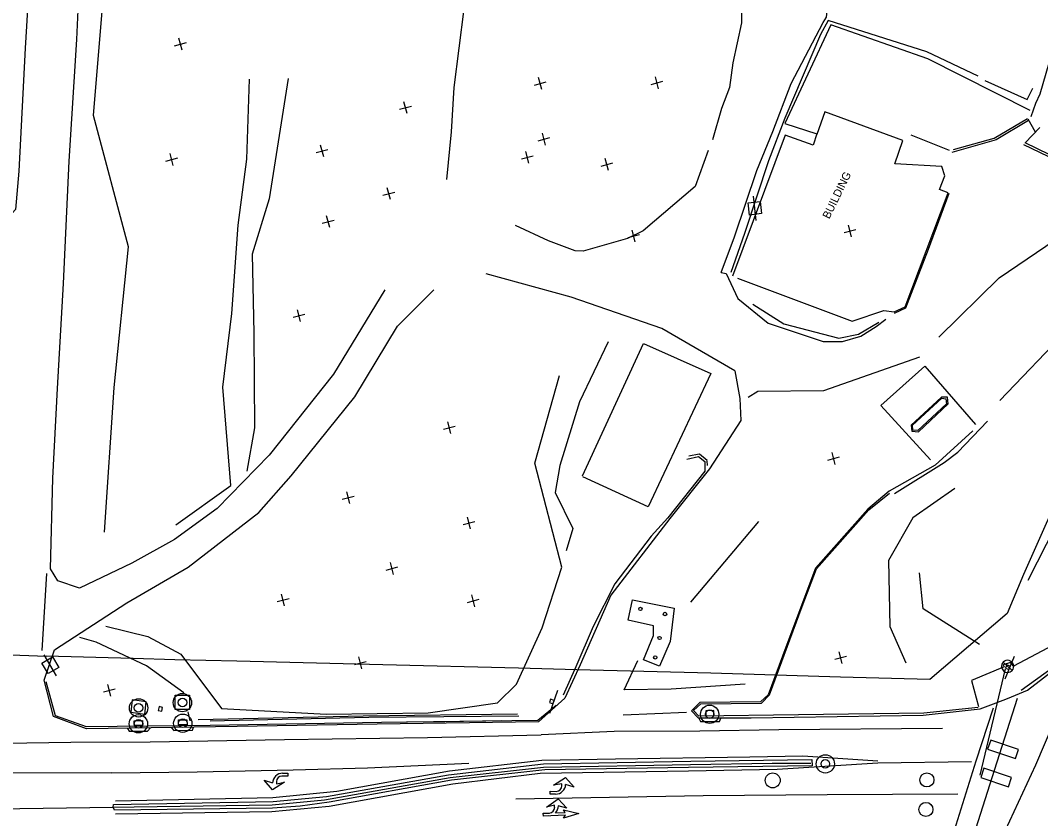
# Model space of a CAD drawing. Extents: x 4711259 to 4716401, y 890074 to 892728.
# Drawn here: x 4712586.5 to 4713004.8, y 891346.1 to 891673.4 of the extents above; entities that cross this region are included whole.
import ezdxf

# ---------------------------------------------------------------- set-up
doc = ezdxf.new("R2010")
doc.units = 0
for name, color, linetype in [('E_GT_WALL_Retaining', 7, 'Continuous'), ('E_HY_STORM_MH', 7, 'Continuous'), ('E_RDWY_PHOTOG_Fence', 7, 'Continuous'), ('E_RDWY_ROAD_Curb', 7, 'Continuous'), ('E_RDWY_ROAD_EdgeAsph', 7, 'Continuous'), ('E_RDWY_ROAD_EdgeConc', 7, 'Continuous'), ('E_RDWY_ROAD_Sidewalk', 7, 'Continuous'), ('E_RDWY_ROAD_Striping', 7, 'Continuous'), ('E_RDWY_ROAD_TBofCurb', 7, 'Continuous'), ('E_TERR_DTM_BrkLines', 7, 'Continuous'), ('E_TERR_DTM_RandomPt', 7, 'Continuous'), ('E_TRAF_PHOTOG_SignalEquipment', 7, 'Continuous'), ('E_TRAF_SIGN_PublicSign', 7, 'Continuous'), ('E_TRAF_SIGNAL_Detector', 7, 'Continuous'), ('E_TRAF_SIGNAL_Equipment', 7, 'Continuous'), ('E_TRAF_SIGNAL_Poles', 7, 'Continuous'), ('E_UTIL_ELEC_POLE', 7, 'Continuous'), ('E_UTIL_MISC_General', 7, 'Continuous')]:
    doc.layers.add(name, color=color, linetype=linetype)

msp = doc.modelspace()

# ---------------------------------------------------------------- linework, layer by layer
at = {"layer": 'E_GT_WALL_Retaining'}
for points in [[(4713000.6, 891636.44), (4712958.58, 891657.64), (4712918.87, 891671.59), (4712899.88, 891631.11), (4712913.06, 891626.79), (4712911.51, 891622.16), (4712900.07, 891626.31), (4712878.42, 891568.51)], [(4712886.81, 891556.96), (4712899.57, 891548.97), (4712922.14, 891543.04), (4712930.16, 891544.73), (4712938.48, 891549.58)], [(4712944.94, 891479.32), (4712965.31, 891492.06), (4712970.91, 891496.37), (4712983.11, 891508.97)], [(4712790.29, 891388.82), (4712726.99, 891388.01), (4712659.31, 891386.58)]]:
    msp.add_lwpolyline(points, dxfattribs=at)
at = {"layer": 'E_HY_STORM_MH'}
for centre, radius in [((4712652.9, 891393.63), 3.75), ((4712634.93, 891391.46), 3.75), ((4712634.93, 891391.46), 1.76), ((4712652.9, 891393.63), 1.76), ((4712869.13, 891388.84), 3.75), ((4712634.85, 891384.94), 3.75), ((4712653.06, 891385.17), 3.75), ((4712869.13, 891388.84), 1.76), ((4712634.85, 891384.94), 1.76), ((4712653.06, 891385.17), 1.76), ((4712916.54, 891368.51), 3.75), ((4712916.54, 891368.51), 1.76)]:
    msp.add_circle(centre, radius, dxfattribs=at)
at = {"layer": 'E_RDWY_PHOTOG_Fence'}
for points in [[(4713045.7, 891553.22), (4713017.05, 891489.52), (4712997.81, 891446.2), (4712991.1, 891430.18)], [(4712991.1, 891430.18), (4712959.4, 891403.14), (4712922.81, 891404.01), (4712869.56, 891405.64), (4712814.66, 891407.03), (4712790.78, 891407.74), (4712735.13, 891409.08), (4712675.26, 891410.61), (4712649.85, 891411.15), (4712632.67, 891411.67), (4712597.09, 891412.69)], [(4712597.22, 891412.51), (4712575.15, 891413.33)]]:
    msp.add_lwpolyline(points, dxfattribs=at)
at = {"layer": 'E_RDWY_ROAD_Curb'}
for p, q in [((4712864.87, 891495.53), (4712860.62, 891494.71)), ((4712868.05, 891492.84), (4712864.95, 891495.54)), ((4712868.16, 891490.86), (4712868.09, 891492.8))]:
    msp.add_line(p, q, dxfattribs=at)
for points in [[(4712999.8, 891632.38), (4712986.67, 891624.45), (4712968.37, 891619.16)], [(4712997.75, 891622.46), (4713007.83, 891617.64), (4713018.22, 891604.67), (4713051.59, 891591.3), (4713075.27, 891585.61), (4713090.25, 891583.37)], [(4712944.91, 891553.35), (4712949.62, 891555.57), (4712958.85, 891579.56), (4712967.29, 891602.46)], [(4712977.01, 891505.08), (4712961.64, 891491.03), (4712942.78, 891480.29), (4712933.91, 891472.94), (4712912.52, 891448.76), (4712900.38, 891416.37), (4712893.05, 891396.84), (4712889.9, 891393.91), (4712865.15, 891393.67), (4712861.69, 891390.31), (4712864.41, 891387.4), (4712886.12, 891387.44), (4712956.66, 891388.43), (4712980.08, 891391.03), (4712986.65, 891393.54), (4712991.2, 891395.3), (4712999.39, 891398.78), (4713017.42, 891412.56), (4713027.96, 891425.91), (4713046.57, 891464.61), (4713070.7, 891516.01), (4713080.81, 891539.89)], [(4712798.86, 891385.79), (4712732.79, 891384.81), (4712675.36, 891383.82), (4712613.58, 891382.94), (4712600.05, 891387.87), (4712596.16, 891402.85)], [(4712624.67, 891351.82), (4712690.06, 891353.11), (4712711.98, 891355.18), (4712762, 891364.01), (4712800.91, 891368.54), (4712861.39, 891369.55), (4712911, 891370.33), (4712911.16, 891367.74), (4712860.5, 891367.03), (4712801.52, 891366.02), (4712763.21, 891361.88), (4712713.08, 891352.78), (4712701.15, 891351.21), (4712689.82, 891350.35), (4712625.05, 891349.47)], [(4712625.05, 891349.47), (4712624.53, 891350.79), (4712624.67, 891351.82)]]:
    msp.add_lwpolyline(points, dxfattribs=at)
at = {"layer": 'E_RDWY_ROAD_EdgeAsph'}
for points in [[(4712735.9, 891562.86), (4712714.82, 891528.34), (4712688.44, 891495.14), (4712667.15, 891473.19), (4712649.72, 891460.53), (4712632.13, 891450.87), (4712610.67, 891440.52), (4712601.83, 891443.5), (4712598.88, 891448.47), (4712599.81, 891485.64), (4712601.62, 891522.38), (4712604.11, 891565.54), (4712606.51, 891615.64), (4712609.62, 891665.6), (4712611.64, 891710.78), (4712614.55, 891772.4), (4712618.2, 891830.11), (4712619.55, 891857.41), (4712617.18, 891894.05), (4712611.49, 891911.96), (4712575.66, 891948.29)], [(4712304.96, 891896.85), (4712384.63, 891896.03), (4712434.12, 891895.34), (4712491.07, 891894.75), (4712543.41, 891894.49), (4712582.4, 891892.24), (4712597.63, 891878.83), (4712597.65, 891831.39), (4712594.45, 891776.63), (4712591.79, 891718.65), (4712588.49, 891662.05), (4712585.87, 891611.48), (4712584.5, 891595.88), (4712574.49, 891585.03), (4712562.61, 891582.71), (4712492.86, 891582.66), (4712437.1, 891583.09), (4712367.74, 891583.27), (4712291.22, 891584.33)], [(4712873.86, 891570.04), (4712879.32, 891584.58), (4712888.45, 891611.83), (4712895.03, 891627.76), (4712902.53, 891647.52), (4712915.63, 891672.52), (4712916.97, 891674.68), (4712918.89, 891692.61), (4712916.93, 891724.02), (4712913.1, 891750.3), (4712909.35, 891767), (4712893.28, 891767.97), (4712893.07, 891774.97), (4712885.3, 891775.81), (4712872.53, 891806.07), (4712863.37, 891828.76), (4712862.6, 891848.83)], [(4712762.03, 891762.78), (4712769.15, 891734.58), (4712770.05, 891707.05), (4712768.24, 891678.07), (4712764.23, 891645.84), (4712763.06, 891627.61), (4712761.25, 891608.18)], [(4712868.48, 891620), (4712863.14, 891605.28), (4712841.8, 891587.08), (4712835.42, 891584), (4712817.31, 891578.73), (4712813.94, 891578.85), (4712803.01, 891582.97), (4712789.55, 891589.23)], [(4712879.42, 891529.63), (4712849.54, 891547.03), (4712812.34, 891559.85), (4712777.44, 891569.45)], [(4712873.86, 891570.04), (4712875.95, 891569.59), (4712880.66, 891559.35), (4712893.11, 891549.27), (4712915.65, 891541.65), (4712923.64, 891541.74), (4712931.17, 891543.91), (4712937.36, 891547.83), (4712941.41, 891550.85)], [(4712596.16, 891402.85), (4712600.49, 891415.33), (4712630.08, 891434.52), (4712655.28, 891449.22), (4712684.3, 891471.52), (4712697.56, 891486.68), (4712723.62, 891519.01), (4712741.1, 891548.01), (4712755.96, 891562.91)], [(4712879.42, 891529.63), (4712881.46, 891518.36), (4712881.84, 891509.32), (4712869.06, 891489.54), (4712852.8, 891469.12), (4712828.62, 891437.64), (4712815.98, 891409.08), (4712809.66, 891395.5), (4712798.86, 891385.79)]]:
    msp.add_lwpolyline(points, dxfattribs=at)
at = {"layer": 'E_RDWY_ROAD_EdgeConc'}
for points in [[(4712944.78, 891553.8), (4712949.28, 891555.96), (4712966.96, 891602.68), (4712963.35, 891604.03), (4712965.58, 891609.68), (4712964.31, 891613.51), (4712945, 891614.56), (4712948.38, 891624.15), (4712916.35, 891635.92), (4712913.1, 891626.52)], [(4712880.49, 891567.73), (4712927.53, 891550.07), (4712940.51, 891554.37), (4712944.78, 891553.8)], [(4712816.96, 891486.57), (4712841.92, 891540.92), (4712869.66, 891528.63), (4712843.93, 891473.89), (4712817.06, 891486.19)], [(4712959.69, 891493.22), (4712939.31, 891515.51), (4712957.4, 891531.52), (4712978.17, 891507.66)], [(4712966.92, 891516.14), (4712966.59, 891518.94), (4712964.22, 891518.93), (4712951.72, 891507.4), (4712952.03, 891504.88), (4712954.77, 891504.71), (4712966.92, 891516.14)], [(4712965.92, 891518.17), (4712966.24, 891516.15), (4712954.5, 891505.15), (4712952.41, 891505.4), (4712952.29, 891507.37), (4712964.29, 891518.48), (4712965.92, 891518.17)], [(4712854.52, 891432.3), (4712852.87, 891418.68), (4712848.51, 891408.58), (4712842.04, 891411.23), (4712846.14, 891421.08), (4712846.04, 891425.05), (4712835.68, 891427.44), (4712837.41, 891435.78), (4712854.52, 891432.3)], [(4712870.89, 891388.26), (4712870.85, 891390.33), (4712867.5, 891390.26), (4712867.54, 891388.5)], [(4712648.47, 891383.33), (4712649.35, 891382.24), (4712657.01, 891382.3), (4712657.52, 891383.56)], [(4712864.63, 891387.24), (4712865.41, 891385.82), (4712873.13, 891385.9), (4712873.73, 891387.22)], [(4712630.42, 891382.96), (4712631.04, 891381.87), (4712638.61, 891381.97), (4712639.76, 891383.22)]]:
    msp.add_lwpolyline(points, dxfattribs=at)
for points in [[(4712649.97, 891396.69), (4712655.85, 891396.7), (4712655.86, 891390.78), (4712649.97, 891390.77)], [(4712638.09, 891393.97), (4712632.36, 891394.7), (4712631.72, 891389.65), (4712637.45, 891388.92)], [(4712633.17, 891386.19), (4712636.51, 891386.23), (4712636.54, 891384.23), (4712633.19, 891384.19)], [(4712651.32, 891386.54), (4712654.76, 891386.58), (4712654.79, 891384.53), (4712651.34, 891384.48)]]:
    msp.add_lwpolyline(points, close=True, dxfattribs=at)
at = {"layer": 'E_RDWY_ROAD_Sidewalk'}
for points in [[(4713000.99, 891633.99), (4713002.92, 891639.47), (4713004.66, 891643.19), (4713010.76, 891664.39)], [(4712967.53, 891619.96), (4712951.73, 891626.33)], [(4713080.07, 891540.26), (4713075.64, 891542.03), (4713072.77, 891537.51), (4713053.95, 891496.36), (4713033.03, 891451.28), (4713024.13, 891432.72), (4713009.94, 891417.21), (4712993.65, 891408.61), (4712992.42, 891410.12), (4712989.47, 891409.11), (4712989.93, 891408.24), (4712976.54, 891402.72), (4712979.39, 891391.98)]]:
    msp.add_lwpolyline(points, dxfattribs=at)
at = {"layer": 'E_RDWY_ROAD_Striping'}
for p, q in [((4712696.2, 891363.51), (4712693.73, 891363.52)), ((4712694.01, 891364.66), (4712696.2, 891364.65)), ((4712696.2, 891364.65), (4712696.2, 891363.51)), ((4712805.14, 891359.72), (4712810.06, 891362.93)), ((4712810.06, 891362.93), (4712813.51, 891358.97)), ((4712689.9, 891357.81), (4712686.44, 891361.77)), ((4712686.44, 891361.77), (4712689.91, 891360.67)), ((4712694.82, 891361.03), (4712689.9, 891357.81)), ((4712691.43, 891361.24), (4712691.43, 891360.38)), ((4712691.43, 891360.38), (4712694.82, 891361.03)), ((4712808.53, 891360.37), (4712805.14, 891359.72)), ((4712808.52, 891359.51), (4712808.53, 891360.37)), ((4712813.51, 891358.97), (4712810.05, 891360.07)), ((4712802.16, 891350.76), (4712806.96, 891354.17)), ((4712803.74, 891356.1), (4712803.75, 891357.25)), ((4712805.93, 891356.09), (4712803.74, 891356.1)), ((4712803.75, 891357.25), (4712806.23, 891357.24)), ((4712806.96, 891354.17), (4712810.56, 891350.35)), ((4712805.52, 891351.54), (4712802.16, 891350.76)), ((4712805.55, 891350.69), (4712805.52, 891351.54)), ((4712810.56, 891350.35), (4712807.05, 891351.31)), ((4712800.87, 891348.24), (4712803.41, 891348.33)), ((4712800.87, 891348.24), (4712803.35, 891348.32)), ((4712800.91, 891347.1), (4712800.87, 891348.24)), ((4712800.91, 891347.1), (4712800.87, 891348.24)), ((4712809.95, 891347.41), (4712800.91, 891347.1)), ((4712803.1, 891347.17), (4712800.91, 891347.1)), ((4712805.9, 891348.41), (4712809.91, 891348.55))]:
    msp.add_line(p, q, dxfattribs=at)
for points in [[(4712977.25, 891338.82), (4712986.96, 891369.37), (4712995.3, 891395.48)], [(4712985.38, 891391.4), (4712978.21, 891369.58), (4712968.72, 891338.99)], [(4712607.13, 891377.36), (4712639.68, 891377.58), (4712694.74, 891378.46), (4712753.37, 891379.33), (4712799.97, 891380.4)], [(4712964.66, 891382.95), (4712897.47, 891382.47), (4712865.15, 891381.89)], [(4712938.13, 891369.63), (4712907.29, 891371.64), (4712885.6, 891371.32), (4712830.57, 891370.46), (4712800.24, 891369.9), (4712762.46, 891365.55), (4712716.18, 891357.15), (4712690.04, 891354.54), (4712625.42, 891353.21)], [(4712625.44, 891348.06), (4712689.53, 891349.03), (4712713.07, 891351.12), (4712763.74, 891360.34), (4712799.58, 891364.65), (4712860.43, 891365.65), (4712896.86, 891366.27), (4712938.1, 891368.94)], [(4712938.1, 891368.94), (4712976.44, 891369.46)], [(4712623.97, 891364.77), (4712658.97, 891365.25), (4712698.37, 891366.04)], [(4712970.86, 891356.05), (4712917.3, 891355.81), (4712866.44, 891355.38), (4712789.61, 891354.07)], [(4712809.91, 891348.55), (4712809.11, 891349.67), (4712815.46, 891348.17)], [(4712815.46, 891348.17), (4712809.23, 891346.24), (4712809.95, 891347.41)]]:
    msp.add_lwpolyline(points, dxfattribs=at)
for centre, radius, start, end in [((4712694, 891360.56), 4.1, 89.8415, 178.5092), ((4712693.72, 891361.23), 2.29, 89.838, 179.832), ((4712805.95, 891360.19), 4.1, 269.7285, 358.3963), ((4712806.24, 891359.52), 2.29, 269.7251, 359.7191), ((4712803.27, 891350.61), 2.29, 271.9834, 1.9773), ((4712802.96, 891351.27), 4.1, 315.8518, 0.6546)]:
    msp.add_arc(centre, radius, start, end, dxfattribs=at)
at = {"layer": 'E_RDWY_ROAD_TBofCurb'}
for p, q in [((4712859.74, 891493.45), (4712864.48, 891494.6)), ((4712864.48, 891494.6), (4712867.19, 891492.56)), ((4712867.19, 891492.56), (4712867.2, 891488.57)), ((4712867.2, 891488.55), (4712851.93, 891469.44)), ((4712851.93, 891469.44), (4712845.17, 891461.86)), ((4712845.17, 891461.86), (4712830.28, 891442.31)), ((4712830.28, 891442.31), (4712821.39, 891424.85)), ((4712821.39, 891424.85), (4712814.22, 891408.27)), ((4712814.22, 891408.27), (4712809.09, 891396.62)), ((4712760.49, 891385.77), (4712744.77, 891385.58)), ((4712783.66, 891386.18), (4712760.51, 891385.77))]:
    msp.add_line(p, q, dxfattribs=at)
for points in [[(4712969.13, 891620.43), (4712985.81, 891625.05), (4712999.51, 891633.09)], [(4713075.53, 891586.52), (4713049.01, 891593.26), (4713018.16, 891605.77), (4713008.37, 891618.43), (4712998.49, 891623.14), (4713004.44, 891629.47)], [(4712996.89, 891398.73), (4713016.34, 891412.82), (4713027.17, 891426.47), (4713029.8, 891431.1), (4713046.51, 891466.8), (4713069.99, 891516.49), (4713078.17, 891535.42), (4713079.89, 891539.92)], [(4712979.24, 891391.63), (4712956.91, 891389.26), (4712905.57, 891388.56), (4712864.73, 891388.06), (4712862.54, 891390.38), (4712865.49, 891393.11), (4712890.35, 891393.39), (4712893.71, 891396.88), (4712907.11, 891433.07), (4712912.87, 891448.51), (4712934.45, 891472.69), (4712942.89, 891479.47)], [(4712596.9, 891402.31), (4712600.75, 891388.38), (4712613.37, 891383.79), (4712664.31, 891384.41), (4712734.58, 891385.56), (4712798.67, 891386.46), (4712806.21, 891392.55)]]:
    msp.add_lwpolyline(points, dxfattribs=at)
at = {"layer": 'E_TERR_DTM_BrkLines'}
for points in [[(4712873.66, 891762.58), (4712878.96, 891748.96), (4712879.73, 891738.18), (4712879.82, 891712.94), (4712881.94, 891696.31), (4712882.13, 891672.43), (4712878.58, 891655.99), (4712877.23, 891645.9), (4712873.94, 891637.19), (4712870.34, 891624.36)], [(4712620.89, 891463.57), (4712624.86, 891522.85), (4712630.79, 891580.47), (4712616.4, 891634.39), (4712620.83, 891687.19), (4712627.84, 891711.72)], [(4712979.16, 891650.47), (4712958.22, 891660.42), (4712917.74, 891673.28), (4712914.63, 891667.52), (4712899.9, 891633.23), (4712893.23, 891615.76), (4712883.35, 891585.96), (4712877.76, 891569.98)], [(4712650.22, 891466.56), (4712672.75, 891482.61), (4712669.51, 891523.03), (4712673.19, 891553.15), (4712675.8, 891589.35), (4712679.28, 891616.53), (4712680.43, 891649.34)], [(4712696.34, 891649.52), (4712688.47, 891600.24), (4712681.5, 891577.48), (4712682.22, 891545.17), (4712682.5, 891506.27), (4712679.36, 891488.57)], [(4712981.97, 891648.77), (4712999.32, 891640.99), (4713001.67, 891645.61)], [(4712999.54, 891632.95), (4713002.6, 891627.69)], [(4712963.09, 891543.44), (4712987.77, 891567.74), (4713010.81, 891583.39), (4713034.58, 891579.02), (4713047.63, 891573.9)], [(4713028.57, 891559.76), (4713016.08, 891546.77), (4712988.05, 891517.52)], [(4712999.71, 891443.83), (4713022.35, 891488.46), (4713030.62, 891508.43), (4713062.16, 891542.81)], [(4712827.53, 891541.63), (4712815.74, 891516.91), (4712807.73, 891490.85), (4712805.82, 891479.85), (4712812.95, 891465), (4712810.26, 891455.91)], [(4712955.11, 891535.26), (4712915.79, 891521.48), (4712888.91, 891521.15), (4712884.95, 891518.68)], [(4712621.45, 891425.01), (4712638.69, 891420.75), (4712652.31, 891413.48), (4712668.9, 891391.26), (4712711.85, 891388.94), (4712753.67, 891389.5), (4712782.15, 891393.54), (4712789.92, 891401.24), (4712800.49, 891424.34), (4712808.45, 891449.2), (4712797.37, 891491.81), (4712807.59, 891527.71)], [(4712969.6, 891481.48), (4712952.43, 891469.38), (4712942.48, 891451.91), (4712942.93, 891424.85), (4712949.61, 891409.87)], [(4712861.38, 891434.78), (4712889.22, 891467.88)], [(4712595.45, 891414.95), (4712597.34, 891446.59)], [(4712979.82, 891417.45), (4712956.64, 891432.05), (4712955.16, 891446.78)], [(4712653.54, 891397.6), (4712638.14, 891408.68), (4712617.52, 891418.37), (4712610.8, 891420.26)], [(4712883.71, 891401.23), (4712853.31, 891399.1), (4712834.04, 891398.87), (4712839.63, 891410.91)], [(4712988.69, 891337.48), (4713002.91, 891368.08), (4713020.16, 891408.83)], [(4712656.07, 891386.12), (4712655.26, 891389.79)], [(4712790.83, 891388.1), (4712729.4, 891387.49), (4712664.32, 891385.98)], [(4712859.64, 891389.52), (4712833.69, 891388.46)], [(4712865.15, 891381.89), (4712829.98, 891381.78), (4712799.97, 891380.4)], [(4712552.23, 891376.18), (4712580.09, 891377.04), (4712607.13, 891377.36)], [(4712624.53, 891350.79), (4712633.12, 891350.84), (4712689.65, 891351.66), (4712711.13, 891353.81), (4712762.65, 891362.9), (4712801.02, 891367.13), (4712861.22, 891368.19), (4712894.8, 891368.73), (4712910.67, 891368.84)], [(4712698.37, 891366.04), (4712728.79, 891366.93), (4712770.33, 891368.8)], [(4712623.97, 891364.77), (4712582, 891364.75), (4712534.38, 891363.33)], [(4712534.67, 891349.09), (4712576.59, 891350.09), (4712624.53, 891350.79)]]:
    msp.add_lwpolyline(points, dxfattribs=at)
at = {"layer": 'E_TERR_DTM_RandomPt'}
for p, q in [((4712649.72, 891662.97), (4712654.55, 891664.24)), ((4712652.77, 891661.19), (4712651.5, 891666.02)), ((4712797.22, 891646.84), (4712802.05, 891648.14)), ((4712800.28, 891645.08), (4712798.99, 891649.91)), ((4712845.12, 891647.13), (4712849.95, 891648.4)), ((4712848.17, 891645.34), (4712846.9, 891650.18)), ((4712745.01, 891635.19), (4712743.73, 891640.03)), ((4712741.95, 891636.98), (4712746.79, 891638.25)), ((4712801.8, 891622.24), (4712800.53, 891627.08)), ((4712710.83, 891617.41), (4712709.53, 891622.24)), ((4712798.75, 891624.03), (4712803.58, 891625.3)), ((4712649.18, 891613.93), (4712647.91, 891618.77)), ((4712707.77, 891619.18), (4712712.6, 891620.47)), ((4712791.97, 891616.56), (4712796.8, 891617.85)), ((4712795.03, 891614.79), (4712793.74, 891619.62)), ((4712646.13, 891615.71), (4712650.96, 891616.98)), ((4712824.56, 891613.65), (4712829.39, 891614.94)), ((4712827.62, 891611.88), (4712826.33, 891616.71)), ((4712735.15, 891601.73), (4712739.99, 891603)), ((4712738.21, 891599.94), (4712736.93, 891604.78)), ((4712713.34, 891588.45), (4712712.05, 891593.28)), ((4712710.28, 891590.22), (4712715.11, 891591.51)), ((4712927.27, 891584.57), (4712926, 891589.41)), ((4712835.55, 891584.33), (4712840.39, 891585.6)), ((4712838.61, 891582.55), (4712837.34, 891587.38)), ((4712924.22, 891586.35), (4712929.05, 891587.62)), ((4712698.31, 891551.65), (4712703.14, 891552.95)), ((4712701.37, 891549.88), (4712700.08, 891554.71)), ((4712759.94, 891505.76), (4712764.78, 891507.03)), ((4712762.99, 891503.98), (4712761.72, 891508.81)), ((4712917.58, 891493.1), (4712922.42, 891494.37)), ((4712920.64, 891491.32), (4712919.37, 891496.15)), ((4712721.54, 891475.25), (4712720.27, 891480.09)), ((4712718.48, 891477.03), (4712723.32, 891478.3)), ((4712768.03, 891466.67), (4712772.86, 891467.94)), ((4712771.08, 891464.88), (4712769.81, 891469.72)), ((4712739.45, 891446.2), (4712738.18, 891451.04)), ((4712736.4, 891447.98), (4712741.23, 891449.26)), ((4712694.83, 891433.29), (4712693.56, 891438.12)), ((4712772.87, 891432.93), (4712771.6, 891437.76)), ((4712691.78, 891435.07), (4712696.62, 891436.34)), ((4712769.82, 891434.71), (4712774.65, 891435.98)), ((4712920.38, 891411.43), (4712925.22, 891412.7)), ((4712923.44, 891409.64), (4712922.17, 891414.48)), ((4712723.45, 891409.27), (4712728.29, 891410.54)), ((4712726.5, 891407.49), (4712725.23, 891412.33)), ((4712623.56, 891396.26), (4712622.29, 891401.1)), ((4712620.51, 891398.04), (4712625.34, 891399.32))]:
    msp.add_line(p, q, dxfattribs=at)
at = {"layer": 'E_TRAF_PHOTOG_SignalEquipment'}
msp.add_lwpolyline([(4712990.35, 891407.53), (4712979.95, 891363.91)], dxfattribs=at)
at = {"layer": 'E_TRAF_SIGN_PublicSign'}
for p, q in [((4712993.94, 891412.5), (4712990.14, 891403.25)), ((4712991.35, 891408.16), (4712991.35, 891408.16)), ((4712806.69, 891398.55), (4712803.42, 891389.1)), ((4712804.35, 891394.07), (4712804.35, 891394.07))]:
    msp.add_line(p, q, dxfattribs=at)
for points in [[(4712992.33, 891408.56), (4712990.94, 891409.13), (4712990.37, 891407.75), (4712991.76, 891407.18)], [(4712805.3, 891394.53), (4712803.89, 891395.02), (4712803.39, 891393.61), (4712804.81, 891393.12)]]:
    msp.add_lwpolyline(points, close=True, dxfattribs=at)
at = {"layer": 'E_TRAF_SIGNAL_Detector'}
for centre, radius in [((4712894.98, 891361.72), 3.05), ((4712958.18, 891361.92), 2.89), ((4712957.8, 891349.83), 2.89)]:
    msp.add_circle(centre, radius, dxfattribs=at)
at = {"layer": 'E_TRAF_SIGNAL_Equipment'}
for p, q in [((4712984.38, 891378.26), (4712983.1, 891374.47)), ((4712995.75, 891374.44), (4712984.38, 891378.26)), ((4712983.11, 891374.47), (4712994.48, 891370.65)), ((4712994.48, 891370.65), (4712995.75, 891374.44)), ((4712981.59, 891366.73), (4712980.3, 891362.94)), ((4712992.95, 891362.86), (4712981.59, 891366.73)), ((4712980.31, 891362.94), (4712991.66, 891359.08)), ((4712991.66, 891359.07), (4712992.95, 891362.86))]:
    msp.add_line(p, q, dxfattribs=at)
at = {"layer": 'E_TRAF_SIGNAL_Poles'}
msp.add_line((4712989.5, 891410.17), (4712993.16, 891406.76), dxfattribs=at)
for start, end in [(136.9384, 316.9344), (316.9344, 136.9384)]:
    msp.add_arc((4712991.33, 891408.47), 2.5, start, end, dxfattribs=at)
at = {"layer": 'E_UTIL_ELEC_POLE'}
for p, q in [((4712888.21, 891591.37), (4712887.08, 891601.3)), ((4712601.32, 891404.65), (4712596.18, 891413.23))]:
    msp.add_line(p, q, dxfattribs=at)
for points in [[(4712885.45, 891593.57), (4712884.88, 891598.54), (4712889.85, 891599.1), (4712890.41, 891594.14)], [(4712597.89, 891405.51), (4712595.32, 891409.8), (4712599.61, 891412.37), (4712602.18, 891408.08)]]:
    msp.add_lwpolyline(points, close=True, dxfattribs=at)
at = {"layer": 'E_UTIL_MISC_General'}
msp.add_lwpolyline([(4712644.8, 891391.67), (4712643.32, 891392), (4712642.98, 891390.41), (4712644.45, 891390.09)], close=True, dxfattribs=at)
for centre, radius in [((4712840.7, 891432.07), 0.689), ((4712850.81, 891429.93), 0.73), ((4712848.57, 891420.12), 0.652), ((4712846.8, 891412.15), 0.709)]:
    msp.add_circle(centre, radius, dxfattribs=at)

# ---------------------------------------------------------------- texts
at = {"layer": 'E_TERR_DTM_RandomPt'}
msp.add_text('BUILDING', height=3.281, rotation=63.9383, dxfattribs=at).set_placement((4712918.16, 891591.71))

doc.saveas('drawing.dxf')
